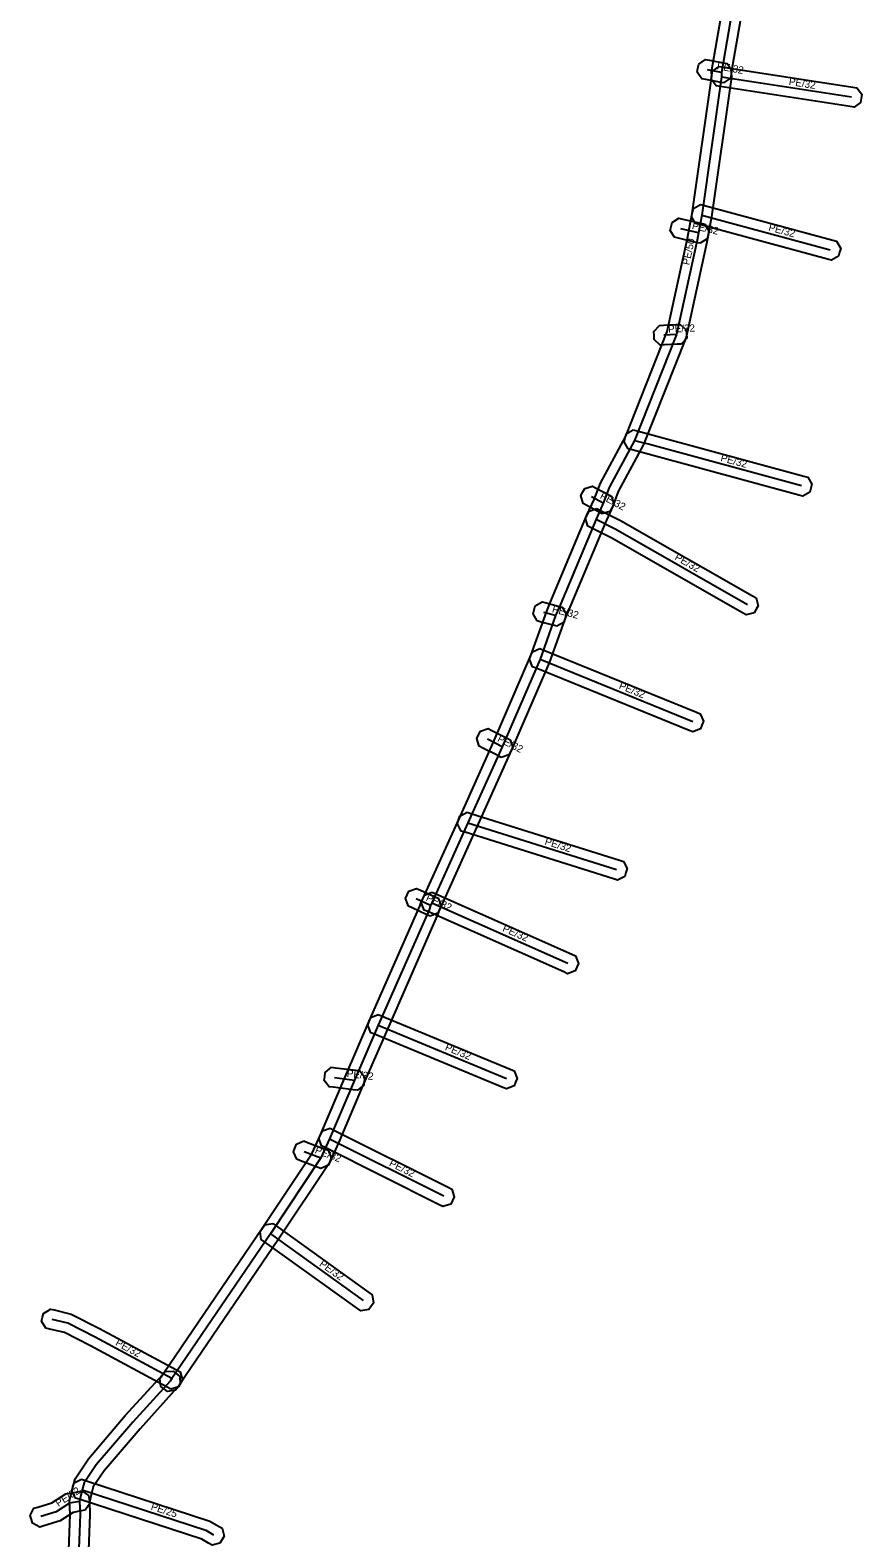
# Model space of a CAD drawing. Extents: x -772893 to -772575, y -1033735 to -1033288.
# Drawn here: x -772892 to -772807.4, y -1033585.9 to -1033432.5 of the extents above; entities that cross this region are included whole.
import ezdxf

# ---------------------------------------------------------------- set-up
doc = ezdxf.new("R2010")
doc.units = 0
for name, color, linetype in [('1', 7, 'Continuous'), ('24', 7, 'Continuous'), ('30', 7, 'Continuous')]:
    doc.layers.add(name, color=color, linetype=linetype)

msp = doc.modelspace()

# ---------------------------------------------------------------- linework, layer by layer
at = {"layer": '1'}
for points in [[(-772819.11, -1033427.71), (-772820.71, -1033436.89), (-772820.69, -1033437.32), (-772822.7, -1033451.51), (-772823.06, -1033453.34), (-772823.2, -1033454.11), (-772825.3, -1033463.78), (-772829.62, -1033474.69), (-772832.2, -1033479.48), (-772832.8, -1033481.04), (-772833.54, -1033482.69), (-772837.3, -1033491.66), (-772837.64, -1033492.46), (-772839.22, -1033496.9), (-772843.09, -1033505.84), (-772846.57, -1033513.6), (-772850.24, -1033521.72), (-772850.35, -1033521.98), (-772850.4, -1033522.04), (-772850.5, -1033522.38), (-772855.68, -1033534.17), (-772858.1, -1033539.74), (-772860.66, -1033545.74), (-772861.58, -1033547.77), (-772866.75, -1033555.56), (-772876.78, -1033570.3), (-772876.97, -1033570.56), (-772877.21, -1033570.9), (-772878.03, -1033571.03), (-772878.36, -1033570.79), (-772878.7, -1033570.55), (-772878.83, -1033569.73), (-772878.59, -1033569.4), (-772878.42, -1033569.16), (-772868.41, -1033554.44), (-772863.34, -1033546.79), (-772862.48, -1033544.94), (-772859.94, -1033538.96), (-772857.52, -1033533.37), (-772852.38, -1033521.66), (-772852.2, -1033521.14), (-772852.1, -1033521), (-772852.06, -1033520.9), (-772848.39, -1033512.78), (-772844.93, -1033505.04), (-772841.08, -1033496.16), (-772839.5, -1033491.74), (-772839.14, -1033490.88), (-772835.38, -1033481.89), (-772834.64, -1033480.27), (-772834.02, -1033478.64), (-772831.44, -1033473.85), (-772827.22, -1033463.2), (-772825.16, -1033453.71), (-772825.02, -1033452.96), (-772824.68, -1033451.18), (-772822.69, -1033437.22), (-772822.71, -1033436.77), (-772821.09, -1033427.39)], [(-772888.75, -1033605.31), (-772887.92, -1033583.57), (-772887.99, -1033582.13), (-772887.85, -1033581.53), (-772887.66, -1033580.81), (-772887.44, -1033579.93), (-772886.08, -1033577.89), (-772882.33, -1033573.5), (-772878.52, -1033569.31), (-772878.24, -1033569), (-772877.42, -1033568.96), (-772877.11, -1033569.24), (-772876.8, -1033569.52), (-772876.76, -1033570.34), (-772877.04, -1033570.65), (-772880.83, -1033574.83), (-772884.49, -1033579.1), (-772885.59, -1033580.75), (-772885.73, -1033581.3), (-772885.91, -1033582.01), (-772885.98, -1033582.31), (-772885.92, -1033583.56), (-772886.75, -1033605.34)]]:
    msp.add_lwpolyline(points, dxfattribs=at)
for points in [[(-772821.48, -1033437.89), (-772821.89, -1033437.81), (-772823.29, -1033437.55), (-772823.7, -1033437.48), (-772824.17, -1033436.8), (-772824.09, -1033436.39), (-772824.02, -1033435.98), (-772823.33, -1033435.51), (-772822.93, -1033435.59), (-772821.53, -1033435.85), (-772821.12, -1033435.92), (-772820.65, -1033436.6), (-772820.73, -1033437.01), (-772820.8, -1033437.42)], [(-772821.95, -1033436.22), (-772821.54, -1033436.28), (-772808.33, -1033438.33), (-772807.92, -1033438.4), (-772807.43, -1033439.06), (-772807.49, -1033439.47), (-772807.56, -1033439.88), (-772808.22, -1033440.37), (-772808.63, -1033440.31), (-772821.84, -1033438.26), (-772822.25, -1033438.2), (-772822.74, -1033437.53), (-772822.68, -1033437.12), (-772822.61, -1033436.71)], [(-772823.83, -1033450.27), (-772823.43, -1033450.38), (-772810.39, -1033453.91), (-772809.99, -1033454.01), (-772809.58, -1033454.73), (-772809.69, -1033455.13), (-772809.79, -1033455.53), (-772810.51, -1033455.94), (-772810.91, -1033455.84), (-772823.95, -1033452.31), (-772824.35, -1033452.2), (-772824.76, -1033451.48), (-772824.66, -1033451.08), (-772824.55, -1033450.68)], [(-772823.86, -1033454.22), (-772824.27, -1033454.12), (-772826.08, -1033453.7), (-772826.48, -1033453.61), (-772826.92, -1033452.91), (-772826.82, -1033452.5), (-772826.73, -1033452.1), (-772826.03, -1033451.66), (-772825.62, -1033451.76), (-772823.81, -1033452.18), (-772823.41, -1033452.27), (-772822.97, -1033452.97), (-772823.07, -1033453.38), (-772823.16, -1033453.78)], [(-772825.8, -1033464.47), (-772826.21, -1033464.49), (-772827.51, -1033464.55), (-772827.93, -1033464.57), (-772828.54, -1033464.01), (-772828.56, -1033463.6), (-772828.58, -1033463.18), (-772828.02, -1033462.57), (-772827.61, -1033462.55), (-772826.31, -1033462.49), (-772825.89, -1033462.47), (-772825.28, -1033463.03), (-772825.26, -1033463.44), (-772825.24, -1033463.86)], [(-772830.68, -1033473.2), (-772830.28, -1033473.3), (-772828.64, -1033473.73), (-772813.31, -1033477.91), (-772812.91, -1033478.01), (-772812.5, -1033478.73), (-772812.6, -1033479.13), (-772812.71, -1033479.53), (-772813.43, -1033479.94), (-772813.83, -1033479.84), (-772829.16, -1033475.67), (-772830.79, -1033475.24), (-772831.19, -1033475.13), (-772831.6, -1033474.42), (-772831.5, -1033474.02), (-772831.39, -1033473.61)], [(-772833.83, -1033481.73), (-772834.2, -1033481.53), (-772835.4, -1033480.88), (-772835.76, -1033480.68), (-772836, -1033479.89), (-772835.8, -1033479.52), (-772835.6, -1033479.16), (-772834.81, -1033478.92), (-772834.44, -1033479.12), (-772833.24, -1033479.77), (-772832.88, -1033479.97), (-772832.64, -1033480.76), (-772832.84, -1033481.13), (-772833.04, -1033481.49)], [(-772834.39, -1033481.21), (-772834.02, -1033481.39), (-772831.97, -1033482.41), (-772818.55, -1033490.09), (-772818.19, -1033490.3), (-772817.98, -1033491.1), (-772818.18, -1033491.46), (-772818.39, -1033491.82), (-772819.19, -1033492.03), (-772819.55, -1033491.83), (-772832.91, -1033484.17), (-772834.9, -1033483.19), (-772835.28, -1033483), (-772835.54, -1033482.22), (-772835.36, -1033481.85), (-772835.17, -1033481.47)], [(-772838.43, -1033493.17), (-772838.83, -1033493.07), (-772840.04, -1033492.75), (-772840.44, -1033492.64), (-772840.85, -1033491.93), (-772840.75, -1033491.52), (-772840.64, -1033491.12), (-772839.93, -1033490.71), (-772839.52, -1033490.81), (-772838.31, -1033491.13), (-772837.91, -1033491.24), (-772837.5, -1033491.96), (-772837.6, -1033492.36), (-772837.71, -1033492.76)], [(-772840.16, -1033495.45), (-772839.77, -1033495.6), (-772824.24, -1033501.93), (-772823.86, -1033502.09), (-772823.54, -1033502.85), (-772823.69, -1033503.24), (-772823.85, -1033503.62), (-772824.61, -1033503.94), (-772825, -1033503.79), (-772840.53, -1033497.46), (-772840.91, -1033497.3), (-772841.23, -1033496.54), (-772841.08, -1033496.15), (-772840.92, -1033495.77)], [(-772844.09, -1033506.52), (-772844.46, -1033506.33), (-772845.96, -1033505.57), (-772846.33, -1033505.39), (-772846.59, -1033504.6), (-772846.4, -1033504.23), (-772846.21, -1033503.86), (-772845.43, -1033503.6), (-772845.06, -1033503.79), (-772843.56, -1033504.55), (-772843.19, -1033504.73), (-772842.93, -1033505.52), (-772843.12, -1033505.89), (-772843.31, -1033506.26)], [(-772847.58, -1033512.11), (-772847.18, -1033512.24), (-772832.07, -1033516.99), (-772831.68, -1033517.11), (-772831.29, -1033517.84), (-772831.42, -1033518.24), (-772831.54, -1033518.64), (-772832.28, -1033519.02), (-772832.67, -1033518.89), (-772847.78, -1033514.14), (-772848.18, -1033514.02), (-772848.56, -1033513.29), (-772848.43, -1033512.89), (-772848.31, -1033512.49)], [(-772851.34, -1033522.67), (-772851.72, -1033522.5), (-772853.16, -1033521.84), (-772853.53, -1033521.67), (-772853.82, -1033520.89), (-772853.65, -1033520.51), (-772853.48, -1033520.14), (-772852.7, -1033519.85), (-772852.32, -1033520.02), (-772850.88, -1033520.68), (-772850.51, -1033520.85), (-772850.22, -1033521.63), (-772850.39, -1033522.01), (-772850.56, -1033522.38)], [(-772851.12, -1033520.23), (-772850.74, -1033520.4), (-772836.91, -1033526.54), (-772836.54, -1033526.7), (-772836.24, -1033527.48), (-772836.41, -1033527.86), (-772836.57, -1033528.23), (-772837.35, -1033528.53), (-772837.73, -1033528.36), (-772851.56, -1033522.22), (-772851.94, -1033522.06), (-772852.23, -1033521.28), (-772852.06, -1033520.9), (-772851.9, -1033520.53)], [(-772856.6, -1033532.69), (-772856.22, -1033532.85), (-772843.18, -1033538.26), (-772842.79, -1033538.42), (-772842.48, -1033539.18), (-772842.64, -1033539.56), (-772842.8, -1033539.95), (-772843.56, -1033540.26), (-772843.94, -1033540.1), (-772856.98, -1033534.69), (-772857.37, -1033534.54), (-772857.68, -1033533.77), (-772857.52, -1033533.39), (-772857.36, -1033533)], [(-772861.35, -1033538.06), (-772860.94, -1033538.11), (-772858.9, -1033538.36), (-772858.49, -1033538.41), (-772857.98, -1033539.06), (-772858.03, -1033539.47), (-772858.08, -1033539.88), (-772858.73, -1033540.39), (-772859.14, -1033540.34), (-772861.18, -1033540.09), (-772861.59, -1033540.04), (-772862.1, -1033539.39), (-772862.05, -1033538.98), (-772862, -1033538.57)], [(-772864.18, -1033545.55), (-772863.79, -1033545.7), (-772862.1, -1033546.35), (-772861.71, -1033546.5), (-772861.38, -1033547.25), (-772861.53, -1033547.64), (-772861.68, -1033548.03), (-772862.43, -1033548.36), (-772862.82, -1033548.21), (-772864.51, -1033547.56), (-772864.9, -1033547.41), (-772865.23, -1033546.66), (-772865.08, -1033546.27), (-772864.93, -1033545.89)], [(-772861.49, -1033544.26), (-772861.12, -1033544.45), (-772849.5, -1033550.26), (-772849.13, -1033550.44), (-772848.87, -1033551.23), (-772849.06, -1033551.6), (-772849.24, -1033551.97), (-772850.03, -1033552.23), (-772850.4, -1033552.04), (-772862.02, -1033546.23), (-772862.39, -1033546.05), (-772862.65, -1033545.26), (-772862.46, -1033544.89), (-772862.28, -1033544.52)], [(-772867.33, -1033553.95), (-772867, -1033554.19), (-772857.56, -1033560.98), (-772857.22, -1033561.22), (-772857.09, -1033562.04), (-772857.33, -1033562.37), (-772857.57, -1033562.71), (-772858.39, -1033562.84), (-772858.72, -1033562.6), (-772868.16, -1033555.81), (-772868.5, -1033555.57), (-772868.63, -1033554.75), (-772868.39, -1033554.42), (-772868.15, -1033554.08)], [(-772877.71, -1033570.81), (-772878.08, -1033570.61), (-772885.88, -1033566.41), (-772888.52, -1033565.05), (-772890.01, -1033564.69), (-772890.41, -1033564.6), (-772890.85, -1033563.89), (-772890.75, -1033563.49), (-772890.66, -1033563.09), (-772889.95, -1033562.65), (-772889.55, -1033562.75), (-772887.82, -1033563.16), (-772884.94, -1033564.64), (-772877.12, -1033568.85), (-772876.76, -1033569.05), (-772876.52, -1033569.84), (-772876.72, -1033570.21), (-772876.92, -1033570.57)], [(-772886.78, -1033579.97), (-772886.39, -1033580.1), (-772873.73, -1033584.23), (-772872.85, -1033584.74), (-772872.49, -1033584.95), (-772872.28, -1033585.75), (-772872.49, -1033586.11), (-772872.7, -1033586.47), (-772873.5, -1033586.68), (-772873.86, -1033586.47), (-772874.56, -1033586.07), (-772887.01, -1033582.01), (-772887.4, -1033581.88), (-772887.77, -1033581.14), (-772887.65, -1033580.74), (-772887.52, -1033580.35)], [(-772886.4, -1033583.13), (-772886.81, -1033583.2), (-772887.64, -1033583.36), (-772888.95, -1033584.19), (-772890.63, -1033584.71), (-772891.03, -1033584.83), (-772891.76, -1033584.44), (-772891.88, -1033584.05), (-772892, -1033583.65), (-772891.62, -1033582.92), (-772891.22, -1033582.8), (-772889.79, -1033582.36), (-772888.39, -1033581.46), (-772887.16, -1033581.24), (-772886.76, -1033581.16), (-772886.08, -1033581.63), (-772886, -1033582.04), (-772885.93, -1033582.45)]]:
    msp.add_lwpolyline(points, close=True, dxfattribs=at)
at = {"layer": '24'}
for points in [[(-772820.1, -1033427.55), (-772821.71, -1033436.83), (-772821.69, -1033437.27), (-772823.69, -1033451.34), (-772824.04, -1033453.15), (-772824.18, -1033453.91), (-772826.26, -1033463.49), (-772830.53, -1033474.27), (-772833.11, -1033479.06), (-772833.72, -1033480.65), (-772834.46, -1033482.29), (-772838.22, -1033491.27), (-772838.57, -1033492.1), (-772840.15, -1033496.53), (-772844.01, -1033505.44), (-772847.48, -1033513.19), (-772851.15, -1033521.31), (-772851.23, -1033521.49), (-772851.3, -1033521.59), (-772851.44, -1033522.02), (-772856.6, -1033533.77), (-772859.02, -1033539.35), (-772861.57, -1033545.34), (-772862.46, -1033547.28), (-772867.58, -1033555), (-772877.6, -1033569.73), (-772877.78, -1033569.98)], [(-772821.71, -1033436.83), (-772823.11, -1033436.57)], [(-772821.69, -1033437.27), (-772808.48, -1033439.32)], [(-772823.69, -1033451.34), (-772810.65, -1033454.87)], [(-772824.04, -1033453.15), (-772825.85, -1033452.73)], [(-772826.26, -1033463.49), (-772827.56, -1033463.55)], [(-772830.53, -1033474.27), (-772828.9, -1033474.7), (-772813.57, -1033478.87)], [(-772833.72, -1033480.65), (-772834.92, -1033480)], [(-772834.46, -1033482.29), (-772832.44, -1033483.29), (-772819.05, -1033490.96)], [(-772838.57, -1033492.1), (-772839.78, -1033491.78)], [(-772840.15, -1033496.53), (-772824.62, -1033502.86)], [(-772844.01, -1033505.44), (-772845.51, -1033504.68)], [(-772847.48, -1033513.19), (-772832.37, -1033517.94)], [(-772851.3, -1033521.59), (-772852.74, -1033520.93)], [(-772851.15, -1033521.31), (-772837.32, -1033527.45)], [(-772856.6, -1033533.77), (-772843.56, -1033539.18)], [(-772861.06, -1033539.1), (-772859.02, -1033539.35)], [(-772861.57, -1033545.34), (-772849.95, -1033551.15)], [(-772864.15, -1033546.63), (-772862.46, -1033547.28)], [(-772867.58, -1033555), (-772858.14, -1033561.79)], [(-772877.6, -1033569.73), (-772885.41, -1033565.52), (-772888.17, -1033564.1), (-772889.78, -1033563.72)], [(-772877.78, -1033569.98), (-772881.58, -1033574.16), (-772885.29, -1033578.5), (-772886.51, -1033580.34), (-772886.7, -1033581.05), (-772886.88, -1033581.77), (-772886.98, -1033582.22), (-772886.92, -1033583.57), (-772887.75, -1033605.33), (-772887.74, -1033605.79), (-772887.89, -1033613.62), (-772888.1, -1033619.09), (-772888.69, -1033627.98)], [(-772886.98, -1033582.22), (-772888.02, -1033582.41), (-772889.37, -1033583.28), (-772890.93, -1033583.75)], [(-772886.7, -1033581.05), (-772874.15, -1033585.15), (-772873.35, -1033585.61)]]:
    msp.add_lwpolyline(points, dxfattribs=at)

# ---------------------------------------------------------------- texts
at = {"layer": '30'}
for s, rotation, p in [('PE/32', 349.4792, (-772822.21, -1033436.5)), ('PE/32', 351.1789, (-772814.89, -1033438.1)), ('PE/32', 346.936, (-772824.75, -1033452.74)), ('PE/32', 344.8528, (-772816.97, -1033452.91)), ('PE/50', 77.7457, (-772824.98, -1033456.48)), ('PE/32', 2.6425, (-772827.11, -1033463.32)), ('PE/32', 344.7784, (-772821.85, -1033476.36)), ('PE/32', 331.5571, (-772834.12, -1033480.13)), ('PE/32', 330.1902, (-772826.52, -1033486.36)), ('PE/32', 345.1865, (-772838.98, -1033491.74)), ('PE/32', 337.8243, (-772832.19, -1033499.5)), ('PE/32', 333.1302, (-772844.56, -1033504.86)), ('PE/32', 342.5489, (-772839.73, -1033515.37)), ('PE/32', 335.3764, (-772851.82, -1033521.06)), ('PE/32', 336.0606, (-772844.04, -1033524.18)), ('PE/32', 337.4675, (-772849.88, -1033536.28)), ('PE/32', 353.0133, (-772859.84, -1033539.03)), ('PE/32', 338.9625, (-772863.11, -1033546.76)), ('PE/32', 333.4349, (-772855.56, -1033548.05)), ('PE/32', 324.2733, (-772862.66, -1033558.2)), ('PE/32', 331.6643, (-772883.4, -1033566.3)), ('PE/32', 32.6324, (-772889.14, -1033582.8)), ('PE/25', 341.9357, (-772879.79, -1033583.04))]:
    msp.add_text(s, height=0.75, rotation=rotation, dxfattribs=at).set_placement(p)

doc.saveas('drawing.dxf')
